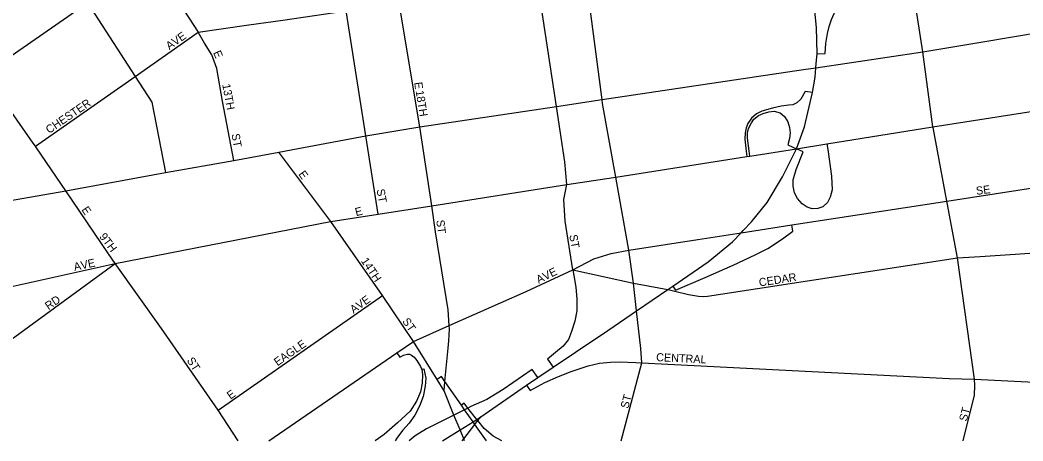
# Model space of a CAD drawing. Extents: x 2139079 to 2262683, y 1235796 to 1334992.
# Drawn here: x 2191123 to 2197328, y 1274636 to 1277243 of the extents above; entities that cross this region are included whole.
import ezdxf

# ---------------------------------------------------------------- set-up
doc = ezdxf.new("R2010")
doc.units = 0
for name, color, linetype in [('GM_X_City_Street', 7, 'Continuous'), ('GM_X_City_Street_Text', 7, 'Continuous'), ('GM_X_Interchange_Ramps', 7, 'Continuous'), ('GM_X_Interstate_Route', 7, 'Continuous'), ('GM_X_US_Route', 7, 'Continuous')]:
    doc.layers.add(name, color=color, linetype=linetype)

msp = doc.modelspace()

# ---------------------------------------------------------------- linework, layer by layer
at = {"layer": 'GM_X_City_Street'}
for points in [[(2196707.8, 1277046.4), (2196591.7, 1277805.3), (2196433.7, 1278846.3), (2196400.2, 1278961.4), (2196370.6, 1279030.8), (2195921, 1279734.8), (2195772.2, 1279967.9), (2195293.5, 1280703)], [(2193771.5, 1275210.6), (2193775.7, 1275255.6), (2193780.2, 1275329.9), (2193778.7, 1275350.1), (2193770.9, 1275448.5), (2193694.2, 1275932), (2193670.2, 1276092.5), (2193597, 1276581.1), (2193469.6, 1277346.7), (2193402.6, 1277828.5), (2193397.8, 1277854.2), (2193390, 1277876.6), (2193377.5, 1277898), (2193360.8, 1277926.4), (2193100.7, 1278341.1)], [(2194722.5, 1276764.2), (2194625.3, 1277504.8)], [(2194441.3, 1276707.4), (2194331.1, 1277443)], [(2191537.6, 1277352.6), (2191539.9, 1277349.1), (2191834.9, 1276894.1)], [(2193262.9, 1276526.3), (2193141.7, 1277299.4)], [(2191217.7, 1276462.1), (2191834.9, 1276894.1), (2192225.1, 1277167.3)], [(2192445.8, 1276373.1), (2192376.4, 1276739.4), (2192340.9, 1276942.5), (2192309.6, 1277026.9), (2192263.3, 1277099.2), (2192225.1, 1277167.3)], [(2196771.9, 1276577), (2196771, 1276582), (2196707.8, 1277046.4)], [(2194795.5, 1276268.4), (2194808.5, 1276270.4), (2195620.1, 1276396.8), (2195639.2, 1276399.7), (2195927.7, 1276444.6), (2196115.4, 1276475.2), (2196771, 1276582), (2199347, 1276984.3), (2199357.6, 1276985.9), (2199452, 1276997.4)], [(2191204.8, 1276480.4), (2190919.6, 1276886.5), (2190911.1, 1276898.6)], [(2191834.9, 1276894.1), (2191938.5, 1276734.3), (2192022.5, 1276299.6)], [(2194888.9, 1275818.3), (2194808.5, 1276270.4), (2194727.4, 1276726.5), (2194724.4, 1276749.7), (2194722.5, 1276764.2)], [(2195316.8, 1275884.2), (2195584.4, 1275925.4), (2195898.5, 1275973.8), (2196857.5, 1276121.5), (2198055.8, 1276306.1), (2199423.7, 1276514.9), (2199975.3, 1276599.1), (2200548.3, 1276694.8), (2200960.1, 1276758.7), (2204353.6, 1276802.7), (2205985.7, 1276739.7), (2208329.5, 1276653.5), (2208438.4, 1276656.1), (2209594.3, 1276683.5), (2210249.4, 1276698.5), (2211015.8, 1276660.8), (2211607.3, 1276645.7), (2211689.1, 1276641.1), (2211782.7, 1276635.3), (2211800.4, 1276631.3)], [(2194507, 1276223.5), (2194493.1, 1276364.1), (2194441.3, 1276707.4)], [(2196859.4, 1276111.4), (2196857.5, 1276121.5), (2196771.9, 1276577)], [(2193339.1, 1276040.6), (2193262.9, 1276526.3)], [(2191406.5, 1276184.9), (2191224.9, 1276451.8), (2191217.7, 1276462.1), (2191204.8, 1276480.4)], [(2193558.3, 1275252.1), (2193364.8, 1275536.2), (2193045.9, 1275994.7), (2192725.1, 1276424.6)], [(2195173.4, 1275563.7), (2195259.9, 1275543.1), (2195320.8, 1275531.8), (2195348.8, 1275529.9), (2195377.3, 1275531.8), (2196923.8, 1275769.9), (2197062.7, 1275778.9), (2197588.4, 1275813.1), (2197889.7, 1275856.3), (2199487.9, 1276121.4), (2200965.1, 1276364.1), (2204362.3, 1276390.1), (2205993.3, 1276295), (2208449.7, 1276154.3), (2211022.8, 1276017.2), (2211423.6, 1275997.3), (2211694.1, 1275984), (2211874.7, 1275974.6), (2211880.2, 1275974.3), (2212100, 1275965.1), (2212268.1, 1275954.8), (2212357.1, 1275951.5)], [(2193043.2, 1275994.2), (2193045.9, 1275994.7), (2193339.1, 1276040.6), (2193670.2, 1276092.5), (2194507, 1276223.5), (2194795.5, 1276268.4)], [(2194542.9, 1275695.9), (2194495.7, 1275997.5), (2194487, 1276131.2), (2194507, 1276223.5)], [(2191670.4, 1275795.7), (2191406.5, 1276184.9)], [(2197028.8, 1275019.3), (2196923.8, 1275769.9), (2196859.4, 1276111.4)], [(2190874.7, 1275548.5), (2191712.1, 1275734.3), (2193043.2, 1275994.2)], [(2194316.7, 1275590.8), (2194542.9, 1275695.9), (2194673.2, 1275763.4), (2194779.9, 1275796.6), (2194888.9, 1275818.3), (2195316.8, 1275884.2)], [(2192473.4, 1274636.1), (2192348.3, 1274827.8), (2191998.7, 1275333.5), (2191712.1, 1275734.3), (2191670.4, 1275795.7)], [(2194918.3, 1275612.3), (2194918.3, 1275612.3), (2194888.9, 1275818.3)], [(2190797.8, 1275069.2), (2191712.1, 1275734.3)], [(2194542.9, 1275695.9), (2194918.3, 1275612.3)], [(2192662, 1274636.1), (2193455, 1275181), (2193558.3, 1275252.1), (2193778.7, 1275350.1), (2194255, 1275562.1), (2194316.7, 1275590.8)], [(2194841.3, 1274636.1), (2194970.6, 1275120.7), (2194963.9, 1275209.3), (2194937.7, 1275441.5), (2194918.3, 1275612.3)], [(2194918.3, 1275612.3), (2194918.3, 1275612.3), (2195020.5, 1275593.8)], [(2195020.5, 1275593.8), (2195131.9, 1275573.6), (2195132.5, 1275573.4), (2195173.4, 1275563.7)], [(2192348.3, 1274827.8), (2193364.8, 1275536.2)], [(2193746.9, 1274945.8), (2193703, 1275017.1), (2193558.3, 1275252.1)], [(2193746.9, 1274945.8), (2193752.2, 1275003.4), (2193771.5, 1275210.6)], [(2194970.6, 1275120.7), (2196871.8, 1275022), (2197028.8, 1275019.3)], [(2196958, 1274636.1), (2197028.8, 1274919.4), (2197031.5, 1274978.6), (2197028.8, 1275019.3)], [(2197028.8, 1275019.3), (2197028.8, 1275019.3), (2199757.3, 1274882.4), (2200984.9, 1274790.2), (2203543.2, 1274790.2), (2203543.2, 1274790.2)], [(2193845.8, 1274704.3), (2193808, 1274796.5), (2193746.9, 1274945.8)], [(2193873.7, 1274636.1), (2193868.7, 1274648.3), (2193845.8, 1274704.3)]]:
    msp.add_lwpolyline(points, dxfattribs=at)
at = {"layer": 'GM_X_Interchange_Ramps'}
for points in [[(2196054.4, 1277033.7), (2196104.9, 1277035), (2196109.6, 1277097.9), (2196118, 1277158.9), (2196129, 1277202.9), (2196143.5, 1277245.1), (2196160.8, 1277283.6), (2196178.9, 1277319.4), (2196207.8, 1277354.3), (2196248.4, 1277390.1), (2196296.3, 1277431.2), (2196328.8, 1277468.7), (2196361.3, 1277515.3), (2196380.4, 1277557.5), (2196391.5, 1277619.4), (2196396.4, 1277713.7), (2196386.8, 1277773.9)], [(2196025.9, 1276794.2), (2195980.5, 1276800.7), (2195954.8, 1276753.2), (2195928.6, 1276729.8), (2195905.1, 1276717.8), (2195880.3, 1276716), (2195832.6, 1276709.9), (2195777.7, 1276697.8), (2195713.2, 1276679.2), (2195679.2, 1276661.8), (2195648, 1276634.6), (2195625.6, 1276602.9), (2195615.5, 1276575.4), (2195608.7, 1276544.6), (2195606.6, 1276505.2), (2195614.8, 1276429.7), (2195620.1, 1276396.8)], [(2195639.2, 1276399.7), (2195633.7, 1276433.2), (2195623.5, 1276510.5), (2195624.7, 1276544.5), (2195630.5, 1276571.8), (2195647.8, 1276606), (2195662.5, 1276628.8), (2195691.2, 1276650.9), (2195719.9, 1276663.5), (2195756.2, 1276675.3), (2195789.9, 1276679), (2195825.4, 1276667.4), (2195852.7, 1276645.6), (2195872.8, 1276613.2), (2195884.7, 1276576.9), (2195887.8, 1276545.1), (2195884.5, 1276510.1), (2195873.5, 1276469.6), (2195927.7, 1276444.6)], [(2196115.4, 1276475.2), (2196121, 1276440.5), (2196144.6, 1276275.1), (2196146.8, 1276191.2), (2196136.4, 1276145.5), (2196118.4, 1276113.2), (2196090.4, 1276086), (2196059.2, 1276074.7), (2196023.6, 1276073.6), (2195992.5, 1276084.6), (2195961.4, 1276105.1), (2195933, 1276136.9), (2195914.7, 1276173.3), (2195906.6, 1276214), (2195906.2, 1276254), (2195925.5, 1276317.4), (2195968.9, 1276425.7), (2195927.7, 1276444.6)], [(2195161.8, 1275593.9), (2195178.4, 1275569.4), (2195362.9, 1275649.3), (2195534.3, 1275724.1), (2195671.2, 1275787.7), (2195750.8, 1275827), (2195841.4, 1275887.9), (2195904.7, 1275936), (2195898.5, 1275973.8)], [(2194542.9, 1275695.9), (2194549.7, 1275661.4), (2194561, 1275588.3), (2194568.8, 1275517), (2194567.1, 1275441.1), (2194556.4, 1275378), (2194535.5, 1275314.1), (2194515.7, 1275263.8), (2194482.5, 1275223.2), (2194435.8, 1275183.7), (2194386.2, 1275142.2), (2194420.6, 1275092.9)], [(2193455, 1275181), (2193472.1, 1275156), (2193495.7, 1275168.4), (2193521.3, 1275173.9), (2193533.5, 1275172.9), (2193545.2, 1275167.3), (2193562.3, 1275154.5), (2193578.5, 1275135.3), (2193600.8, 1275097.8), (2193608.2, 1275078.7), (2193613.4, 1275046.9), (2193610.5, 1274993.7), (2193601.4, 1274940.3), (2193575.5, 1274883.5), (2193536.2, 1274821.5), (2193458.6, 1274747.4), (2193375.1, 1274675.4), (2193320.4, 1274636.1)], [(2194256, 1274980.9), (2194280, 1274948.3), (2194370.8, 1274997.1), (2194454.9, 1275035.6), (2194533, 1275065.8), (2194638, 1275101.7), (2194707.8, 1275118.1), (2194777.3, 1275123.6), (2194832.9, 1275125.2), (2194932.7, 1275121.5), (2194970.6, 1275120.7)], [(2193608.2, 1275078.7), (2193621, 1275082.4), (2193633.2, 1275024.6), (2193629.1, 1274974.9), (2193617.6, 1274912.4), (2193594.7, 1274851), (2193566.6, 1274794.8), (2193531.1, 1274747), (2193488.7, 1274700.4), (2193455.1, 1274654), (2193444.9, 1274636.1)], [(2194326.2, 1275029.8), (2194292.2, 1275079.5), (2194111.2, 1274955.6), (2194011.9, 1274893.8), (2193913.2, 1274849.5), (2193894.6, 1274840.1), (2193873.6, 1274829.5), (2193808, 1274796.5), (2193724.6, 1274754.3), (2193638.4, 1274710.4), (2193568.6, 1274667.3), (2193530.7, 1274636.1)], [(2194008.5, 1274636.1), (2193937.7, 1274737.5), (2193925.9, 1274754.5), (2193873.6, 1274829.5), (2193854.4, 1274857), (2193752.2, 1275003.4), (2193730.3, 1275034.8), (2193703, 1275017.1)], [(2194103.1, 1274636.1), (2194050.7, 1274665.6), (2193994.5, 1274713.6), (2193956.4, 1274761.8), (2193950.1, 1274769.8), (2193894.6, 1274840.1), (2193870.9, 1274870.2), (2193854.4, 1274857)]]:
    msp.add_lwpolyline(points, dxfattribs=at)
at = {"layer": 'GM_X_Interstate_Route'}
for points in [[(2196049.8, 1276973.5), (2196054.4, 1277033.7), (2196051.8, 1277197.3), (2196038.3, 1277318.3), (2196008.7, 1277470.1), (2195950.6, 1277681.7)], [(2195597.3, 1275938.8), (2195649.1, 1275992.2), (2195745, 1276113), (2195840.9, 1276272.5), (2195927.7, 1276444.6), (2195977.6, 1276580.6), (2196025.9, 1276794.2), (2196043.2, 1276888.3), (2196047.8, 1276947.6), (2196049.8, 1276973.5)], [(2194726.7, 1275297.9), (2194937.7, 1275441.5), (2195131.9, 1275573.6), (2195161.8, 1275593.9), (2195380.3, 1275746.1), (2195530.8, 1275870.1), (2195584.4, 1275925.4), (2195597.3, 1275938.8)], [(2193952.4, 1274771.2), (2193974.4, 1274785), (2194256, 1274980.9), (2194326.2, 1275029.8), (2194420.6, 1275092.9), (2194697.7, 1275278.2), (2194726.7, 1275297.9)], [(2193859.3, 1274636.1), (2193868.7, 1274648.3), (2193937.7, 1274737.5), (2193956.4, 1274761.8), (2193974.4, 1274785)], [(2193737.2, 1274636.1), (2193845.8, 1274704.3), (2193925.9, 1274754.5), (2193950.1, 1274769.8), (2193952.4, 1274771.2)]]:
    msp.add_lwpolyline(points, dxfattribs=at)
at = {"layer": 'GM_X_US_Route'}
for points in [[(2191921.2, 1277613.3), (2192078.6, 1277394.3), (2192225.1, 1277167.3)], [(2192748.1, 1277242.7), (2193141.7, 1277299.4), (2193469.6, 1277346.7), (2194328.1, 1277463), (2194625.3, 1277504.8), (2194736.8, 1277520.8)], [(2195969.9, 1276936), (2196047.8, 1276947.6), (2196707.8, 1277046.4), (2197067.5, 1277105.1), (2197459.1, 1277172.2), (2197818.7, 1277230.9), (2198078.5, 1277272.2), (2198354.2, 1277321.9), (2198679.9, 1277376.1), (2199011.5, 1277434.5), (2199231.3, 1277471.3), (2199236.5, 1277472.2), (2199237.4, 1277472.4)], [(2190916.6, 1276917.3), (2191539.9, 1277349.1), (2191571.8, 1277371.2)], [(2192225.1, 1277167.3), (2192538.9, 1277212.6)], [(2192538.9, 1277212.6), (2192748.1, 1277242.7)], [(2194441.3, 1276707.4), (2194724.4, 1276749.7), (2195969.9, 1276936)], [(2192844.5, 1276447.1), (2193262.9, 1276526.3), (2193597, 1276581.1), (2194441.3, 1276707.4)], [(2191406.5, 1276184.9), (2192022.5, 1276299.6), (2192445.8, 1276373.1), (2192725.1, 1276424.6), (2192844.5, 1276447.1)], [(2189879.5, 1275910), (2189882.7, 1275912.6), (2190728.9, 1276066.6), (2191406.5, 1276184.9)]]:
    msp.add_lwpolyline(points, dxfattribs=at)

# ---------------------------------------------------------------- texts
at = {"layer": 'GM_X_City_Street_Text'}
for s, rotation, p in [('AVE', 35.31652, (2192046.8, 1277056)), ('E', 293.25693, (2192316.7, 1277041.4)), ('13TH', 280.62131, (2192373.8, 1276843.2)), ('E', 277.12166, (2193561.9, 1276855.9)), ('18TH', 279.16479, (2193570.7, 1276803.4)), ('CHESTER', 34.45938, (2191303.3, 1276536.8)), ('ST', 280.61472, (2192431, 1276535.2)), ('E', 305.54359, (2192843, 1276288.1)), ('SE', 7.12165, (2197040.6, 1276160)), ('ST', 280.62791, (2193328.6, 1276192)), ('E', 303.69848, (2191501.2, 1276067.9)), ('E', 14.04909, (2193202.7, 1276027.8)), ('ST', 277.13512, (2193698.3, 1276002.2)), ('9TH', 306.86816, (2191610.9, 1275901.1)), ('ST', 280.62543, (2194521, 1275910.4)), ('14TH', 303.69568, (2193230.4, 1275751.1)), ('AVE', 12.09582, (2191460.6, 1275689.1)), ('AVE', 26.56505, (2194331.6, 1275609.1)), ('CEDAR', 8.65224, (2195698.4, 1275592.4)), ('RD', 34.51432, (2191298.9, 1275445.6)), ('AVE', 35.31045, (2193186.4, 1275423.6)), ('ST', 304.70215, (2193485.5, 1275377.2)), ('EAGLE', 34.82713, (2192715.6, 1275098)), ('ST', 302.73208, (2192152.5, 1275135)), ('CENTRAL', 357.31766, (2195057.8, 1275130.5)), ('E', 35.54358, (2192425.1, 1274891.1)), ('ST', 75.07583, (2194885.5, 1274833.1)), ('ST', 75.06222, (2196979.9, 1274753.9))]:
    msp.add_text(s, height=50, rotation=rotation, dxfattribs=at).set_placement(p)

doc.saveas('drawing.dxf')
